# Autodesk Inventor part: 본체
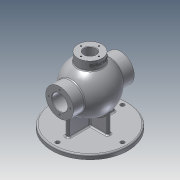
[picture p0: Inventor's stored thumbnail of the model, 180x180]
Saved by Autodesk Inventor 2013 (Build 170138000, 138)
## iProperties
Created: 2020-08
Part Number: 본체
Material: 알루미늄 6061
Document SubType Name: Modeling
Designer: user
Density: 1 g/cm^3
Author: user
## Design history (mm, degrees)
sketch "스케치1"
  geometry: L1 (0, 53)-(0, -53); A1 r 53 centre (0, 0) between (0, -53) and (0, 53); 2 further points
  constraints: 2 end point, 2 point on circle, 2 vertical alignment, 1 centre point, 1 coincident, 1 midpoint, 1 vertical
  dimensions: "d81" = 53 radius of A1
revolve "회전1" sketch "스케치1" stored, may be unused: angle "d4" = 90 deg
node "작업 평면1"
sketch "스케치3"
  geometry: C1 r 31 at (0, 0); 1 further point
  constraints: 1 centre point, 1 coincident
  dimensions: "d9" = 62 diameter of C1
extrude "돌출1" join sketch "스케치3" distance "d10" = 136; taper "d11" = 0 deg
sketch "스케치2"
  geometry: L1 (0, 43)-(0, -43); A1 r 43 centre (0, 0) between (0, -43) and (0, 43); 2 further points
  constraints: 2 end point, 2 point on circle, 1 centre point, 1 coincident, 1 midpoint, 1 vertical alignment
  dimensions: "d5" = 43 radius of A1; "d6" = 86 distance of L1.start L1.end
revolve "회전2" sketch "스케치2" stored, may be unused: angle "d7" = 90 deg
node "작업 평면2"
sketch "스케치5"
  geometry: C1 r 27 at (0, 0); 1 further point
  constraints: 1 centre point, 1 coincident
  dimensions: "d20" = 54 diameter of C1
extrude "돌출2" join sketch "스케치5" stored distance "d21" = 136; taper "d22" = 0 deg
sketch "스케치6"
  geometry: C1 r 27 at (0, 0) reference; C2 r 13 at (0, 0)
  constraints: 1 centre point, 1 coincident
  dimensions: "d23" = 26 diameter of C2
extrude "돌출3" cut sketch "스케치6" stored distance "d24" = 136; taper "d25" = 0 deg
node "작업 평면3"
sketch "스케치7"
  geometry: C1 r 85 at (0, 0); 1 further point
  constraints: 1 centre point, 1 coincident
  dimensions: "d27" = 170 diameter of C1
extrude "돌출4" join sketch "스케치7" distance "d28" = 10; taper "d29" = 0 deg
sketch "스케치8"
  geometry: L1 (-52, 4)-(52, 4); L2 (52, 4)-(52, -4); L3 (52, -4)-(-52, -4); L4 (-52, -4)-(-52, 4); L5 (-4, 43)-(4, 43); L6 (4, 43)-(4, -43); L7 (4, -43)-(-4, -43); L8 (-4, -43)-(-4, 43); L9 (-52, 0)-(52, 0); L10 (0, 43)-(0, -43); C1 r 85 at (0, 0) reference; 1 further point
  constraints: 20 end point, 6 midpoint, 4 parallel, 2 horizontal, 2 perpendicular, 1 coincident
  dimensions: "d30" = 8 distance of L5.start L5.end; "d32" = 8 distance of L3.end L1.start; "d33" = 104 distance of L1.start L1.end; "d34" = 86 distance of L5.end L6.end
extrude "돌출5" join sketch "스케치8" stored distance "d35" = 10; taper "d36" = 0 deg
sketch "스케치4"
  geometry: L1 (-68, -31)-(-68, 31) reference; L2 (-68, 31)-(-42.988, 31) reference; L3 (42.988, 31)-(68, 31) reference; L4 (68, 31)-(68, -31) reference; L5 (68, -31)-(42.988, -31) reference; L6 (-42.988, -31)-(-68, -31) reference; L7 (-68, 0)-(68, 0); L8 (-68, 0)-(-68, 17.5); L9 (-68, 17.5)-(-52, 17.5); L10 (-52, 17.5)-(-52, 18.5); L11 (-52, 18.5)-(-50.25, 18.5); L12 (-50.25, 18.5)-(-50.25, 17.5); L13 (-50.25, 17.5)-(68, 17.5); L14 (68, 17.5)-(68, 0); C1 r 43 at (0, 0) reference; A1 r 53 centre (0, 0) between (42.988, 31) and (-42.988, 31) reference; A2 r 53 centre (0, 0) between (-42.988, -31) and (42.988, -31) reference; 1 further point
  constraints: 16 end point, 3 perpendicular, 2 midpoint, 2 parallel, 2 point on line, 1 collinear
  dimensions: "d12" = 35 diameter of L9 L7; "d14" = 16 distance of L8.end L9.end; "d15" = 37 diameter of L11 L7; "d16" = 1.75 distance of L10.end L11.end; "d17" = 35 diameter of L13 L7
revolve "회전3" sketch "스케치4" stored, may be unused: angle "d18" = 90 deg
node "작업 평면4"
sketch "스케치9"
  geometry: L1 (27, -65)-(27, -45.607) reference; L2 (27, -65)-(-27, -65) reference; 2 further points
  constraints: 1 other
  dimensions: "d38" = 9 distance from line of L2 point (0, -56); "d39" = 27 distance from line of L1 point (0, -56)
feature "엠보싱1" sketch "스케치9" dims "d12" = 35, "d14" = 16, "d15" = 37, "d16" = 1.75, "d17" = 35, "d40" = 0.5, "d41" = 0
sketch "스케치10" dims "d42" = 48
  geometry: C1 r 17.5 at (0, 0) reference; C2 r 31 at (0, 0) reference; 2 further points
  constraints: 2 vertical alignment, 1 coincident, 2 other
hole "구멍1" sketch "스케치10" at (0, 24) diameter "d43" = 3.242; stored, may be unused: countersink angle "d47" = 90 deg, drill point angle "d49" = 118 deg; dims "d44" = 12, "d45" = 4, "d46" = 2, "d48" = 15
sketch "스케치11" dims "d53" = 40
  geometry: C1 r 13 at (0, 0) reference; C2 r 27 at (0, 0) reference; 2 further points
  constraints: 2 vertical alignment, 1 coincident, 2 other
hole "구멍2" sketch "스케치11" at (0, 20) diameter "d54" = 3.242; stored, may be unused: countersink angle "d58" = 90 deg, drill point angle "d60" = 118 deg; dims "d55" = 12, "d56" = 4, "d57" = 2, "d59" = 15
sketch "스케치12" dims "d64" = 145
  geometry: C1 r 85 at (0, 0) reference; 2 further points
  constraints: 2 vertical alignment, 1 coincident, 2 other
hole "구멍3" sketch "스케치12" at (0, 72.5) diameter "d65" = 9; stored, may be unused: countersink angle "d69" = 90 deg, drill point angle "d71" = 118 deg; dims "d66" = 12, "d67" = 4, "d68" = 2, "d70" = 15
chamfer "모따기1" distance "d75" = 1; stored, may be unused: second distance "d76" = 2, angle "d77" = 45 deg
fillet "모깎기1" dims "d78" = 3
fillet "모깎기2" dims "d79" = 3
fillet "모깎기3" dims "d80" = 3
node "솔리드1"
pattern_circular "원형 패턴1" dims angle "d51" = 360 deg
mirror "대칭1"
pattern_circular "원형 패턴2" dims angle "d62" = 360 deg
pattern_circular "원형 패턴3" dims angle "d73" = 360 deg
node "절단 모서리 투영1"
other parameters: "d8" = 68, "d19" = -65, "d26" = 85, "d37" = -28
